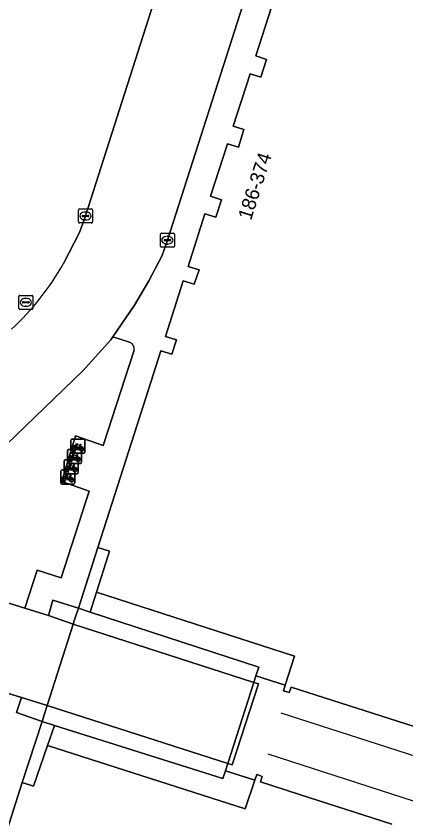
# Model space of a CAD drawing. Extents: x 160675 to 161153, y 383241 to 383714.
# Drawn here: x 160812.1 to 160839.9, y 383336.8 to 383394.1 of the extents above; entities that cross this region are included whole.
import ezdxf

# ---------------------------------------------------------------- set-up
doc = ezdxf.new("R2010")
doc.units = 0
for name, color, linetype in [('IMGEO_Brandkraan', 7, 'Continuous'), ('IMGEO_Erf', 7, 'Continuous'), ('IMGEO_Fietsenrek', 7, 'Continuous'), ('IMGEO_Grasland_overig', 7, 'Continuous'), ('IMGEO_Groenvoorziening', 7, 'Continuous'), ('IMGEO_Kolk', 7, 'Continuous'), ('IMGEO_Lijnafwatering', 7, 'Continuous'), ('IMGEO_Muur', 7, 'Continuous'), ('IMGEO_Pand', 7, 'Continuous'), ('IMGEO_Pand_nummerreeks', 7, 'Continuous'), ('IMGEO_Pand_overbouw', 7, 'Continuous'), ('IMGEO_Rijbaan_lokaal_gesloten', 7, 'Continuous'), ('IMGEO_Rijbaan_lokaal_open', 7, 'Continuous'), ('IMGEO_Voetpad_open', 7, 'Continuous')]:
    doc.layers.add(name, color=color, linetype=linetype)

msp = doc.modelspace()

# ---------------------------------------------------------------- linework, layer by layer
at = {"layer": 'IMGEO_Brandkraan'}
for p, q in [((160812.259, 383373.243), (160812.259, 383374.095)), ((160812.334, 383374.169), (160813.186, 383374.169)), ((160812.518, 383373.663), (160812.518, 383373.675)), ((160812.561, 383373.712), (160812.959, 383373.712)), ((160812.747, 383373.949), (160812.772, 383373.949)), ((160813.002, 383373.675), (160813.002, 383373.663)), ((160813.26, 383374.095), (160813.26, 383373.243)), ((160813.186, 383373.169), (160812.334, 383373.169)), ((160812.956, 383373.626), (160812.558, 383373.626)), ((160812.77, 383373.389), (160812.745, 383373.389))]:
    msp.add_line(p, q, dxfattribs=at)
for points in [[(160812.259, 383373.243), (160812.259, 383374.095)], [(160812.334, 383374.169), (160813.186, 383374.169)], [(160813.26, 383374.095), (160813.26, 383373.243)], [(160813.186, 383373.169), (160812.334, 383373.169)]]:
    msp.add_lwpolyline(points, dxfattribs=at)
for centre, radius, start, end in [((160812.336, 383374.093), 0.0765, 91.552, 178.448), ((160812.336, 383374.093), 0.0765, 91.552, 178.448), ((160812.558, 383373.672), 0.0403, 85.8775, 175.7526), ((160812.555, 383373.662), 0.0366, 178.938, 274.7102), ((160812.959, 383373.669), 0.043, 264.8664, 352.4533), ((160812.963, 383373.674), 0.0386, 1.7309, 96.639), ((160813.184, 383374.093), 0.0765, 1.552, 88.448), ((160813.184, 383374.093), 0.0765, 1.552, 88.448), ((160812.336, 383373.245), 0.0765, 181.552, 268.448), ((160812.336, 383373.245), 0.0765, 181.552, 268.448), ((160813.184, 383373.245), 0.0765, 271.552, 358.448), ((160813.184, 383373.245), 0.0765, 271.552, 358.448)]:
    msp.add_arc(centre, radius, start, end, dxfattribs=at)
for centre, major_axis, ratio, start_param, end_param in [((160812.746, 383373.669), (-0.387, 0.002), 0.722429, 4.712389, 7.853982), ((160812.771, 383373.669), (-0.39, 0.002), 0.717154, 1.570796, 4.712389)]:
    msp.add_ellipse(centre, major_axis=major_axis, ratio=ratio, start_param=start_param, end_param=end_param, dxfattribs=at)
at = {"layer": 'IMGEO_Erf'}
msp.add_lwpolyline([(160815.453, 383376.434), (160816.581, 383378.652), (160817.019, 383379.826), (160822.806, 383397.984)], dxfattribs=at)
msp.add_arc((160797.755, 383386.651), 20.436, 313.2153, 330.002, dxfattribs=at)
at = {"layer": 'IMGEO_Fietsenrek'}
for p, q in [((160816.041, 383363.919), (160816.882, 383363.919)), ((160816.882, 383363.919), (160816.041, 383363.919)), ((160815.966, 383362.994), (160815.966, 383363.835)), ((160815.966, 383363.835), (160815.966, 383362.994)), ((160816.653, 383363.468), (160816.689, 383363.373)), ((160816.966, 383363.844), (160816.966, 383363.003)), ((160816.966, 383363.003), (160816.966, 383363.844)), ((160815.728, 383362.262), (160815.728, 383363.103)), ((160815.728, 383363.103), (160815.728, 383362.262)), ((160815.803, 383363.187), (160816.644, 383363.187)), ((160816.644, 383363.187), (160815.803, 383363.187)), ((160816.891, 383362.919), (160816.05, 383362.919)), ((160816.05, 383362.919), (160816.891, 383362.919)), ((160816.093, 383363.003), (160816.132, 383363.163)), ((160816.127, 383363.003), (160816.093, 383363.003)), ((160816.162, 383363.151), (160816.127, 383363.003)), ((160816.204, 383363.175), (160816.203, 383363.179)), ((160816.245, 383363.003), (160816.211, 383363.145)), ((160816.235, 383363.186), (160816.236, 383363.179)), ((160816.243, 383363.149), (160816.278, 383363.003)), ((160816.278, 383363.003), (160816.245, 383363.003)), ((160816.728, 383363.112), (160816.728, 383362.271)), ((160816.728, 383362.271), (160816.728, 383363.112)), ((160815.491, 383361.53), (160815.491, 383362.371)), ((160815.491, 383362.371), (160815.491, 383361.53)), ((160815.566, 383362.455), (160816.407, 383362.455)), ((160816.407, 383362.455), (160815.566, 383362.455)), ((160815.855, 383362.271), (160815.894, 383362.431)), ((160815.889, 383362.271), (160815.855, 383362.271)), ((160815.924, 383362.419), (160815.889, 383362.271)), ((160815.966, 383362.443), (160815.965, 383362.447)), ((160816.007, 383362.271), (160815.973, 383362.413)), ((160815.997, 383362.454), (160815.998, 383362.447)), ((160816.005, 383362.417), (160816.04, 383362.271)), ((160816.04, 383362.271), (160816.007, 383362.271)), ((160816.415, 383362.736), (160816.451, 383362.641)), ((160816.491, 383362.38), (160816.491, 383361.539)), ((160816.491, 383361.539), (160816.491, 383362.38)), ((160815.253, 383360.798), (160815.253, 383361.639)), ((160815.253, 383361.639), (160815.253, 383360.798)), ((160815.328, 383361.723), (160816.169, 383361.723)), ((160816.169, 383361.723), (160815.328, 383361.723)), ((160815.618, 383361.539), (160815.657, 383361.699)), ((160815.687, 383361.687), (160815.652, 383361.539)), ((160815.729, 383361.711), (160815.728, 383361.715)), ((160815.77, 383361.539), (160815.736, 383361.681)), ((160815.76, 383361.722), (160815.761, 383361.715)), ((160815.768, 383361.685), (160815.803, 383361.539)), ((160816.653, 383362.187), (160815.812, 383362.187)), ((160815.812, 383362.187), (160816.653, 383362.187)), ((160816.178, 383362.004), (160816.214, 383361.909)), ((160816.253, 383361.648), (160816.253, 383360.807)), ((160816.253, 383360.807), (160816.253, 383361.648)), ((160816.416, 383361.455), (160815.575, 383361.455)), ((160815.575, 383361.455), (160816.416, 383361.455)), ((160815.652, 383361.539), (160815.618, 383361.539)), ((160815.803, 383361.539), (160815.77, 383361.539)), ((160815.94, 383361.272), (160815.976, 383361.177)), ((160816.178, 383360.723), (160815.337, 383360.723)), ((160815.337, 383360.723), (160816.178, 383360.723)), ((160815.38, 383360.807), (160815.419, 383360.967)), ((160815.414, 383360.807), (160815.38, 383360.807)), ((160815.449, 383360.955), (160815.414, 383360.807)), ((160815.491, 383360.979), (160815.49, 383360.983)), ((160815.532, 383360.807), (160815.498, 383360.949)), ((160815.522, 383360.99), (160815.523, 383360.983)), ((160815.53, 383360.953), (160815.565, 383360.807)), ((160815.565, 383360.807), (160815.532, 383360.807))]:
    msp.add_line(p, q, dxfattribs=at)
for points in [[(160816.3, 383363.393), (160816.248, 383363.303), (160816.208, 383363.278), (160816.209, 383363.325), (160816.264, 383363.419)], [(160816.279, 383363.445), (160816.374, 383363.609), (160816.46, 383363.595), (160816.462, 383363.586), (160816.406, 383363.575), (160816.379, 383363.53), (160816.635, 383363.489)], [(160816.575, 383363.201), (160816.525, 383363.201), (160816.334, 383363.452), (160816.315, 383363.42)], [(160816.622, 383363.464), (160816.365, 383363.505), (160816.348, 383363.476), (160816.515, 383363.256), (160816.622, 383363.464)], [(160816.67, 383363.366), (160816.64, 383363.443), (160816.531, 383363.225), (160816.574, 383363.225)], [(160816.604, 383363.225), (160816.724, 383363.224), (160816.68, 383363.338)], [(160816.7, 383363.345), (160816.755, 383363.2), (160816.605, 383363.2)], [(160816.635, 383363.489), (160816.66, 383363.538), (160816.654, 383363.542), (160816.631, 383363.546), (160816.619, 383363.553), (160816.618, 383363.556), (160816.62, 383363.561), (160816.715, 383363.546), (160816.717, 383363.536), (160816.707, 383363.523), (160816.695, 383363.517), (160816.681, 383363.523), (160816.653, 383363.468)], [(160816.041, 383362.713), (160816.136, 383362.877), (160816.222, 383362.863), (160816.224, 383362.854), (160816.168, 383362.843), (160816.141, 383362.798), (160816.397, 383362.757)], [(160816.384, 383362.732), (160816.127, 383362.773), (160816.11, 383362.744), (160816.277, 383362.524), (160816.384, 383362.732)], [(160816.397, 383362.757), (160816.422, 383362.806), (160816.416, 383362.81), (160816.393, 383362.814), (160816.381, 383362.821), (160816.38, 383362.824), (160816.382, 383362.829), (160816.477, 383362.814), (160816.479, 383362.804), (160816.469, 383362.791), (160816.457, 383362.785), (160816.443, 383362.791), (160816.415, 383362.736)], [(160816.062, 383362.661), (160816.01, 383362.571), (160815.97, 383362.546), (160815.971, 383362.593), (160816.026, 383362.687)], [(160816.337, 383362.469), (160816.287, 383362.469), (160816.096, 383362.72), (160816.077, 383362.688)], [(160816.432, 383362.634), (160816.402, 383362.711), (160816.293, 383362.493), (160816.336, 383362.493)], [(160816.366, 383362.493), (160816.486, 383362.492), (160816.442, 383362.606)], [(160816.462, 383362.613), (160816.517, 383362.468), (160816.367, 383362.468)], [(160815.825, 383361.929), (160815.773, 383361.839), (160815.733, 383361.814), (160815.734, 383361.861), (160815.789, 383361.955)], [(160815.804, 383361.981), (160815.899, 383362.145), (160815.985, 383362.131), (160815.987, 383362.122), (160815.931, 383362.111), (160815.904, 383362.066), (160816.16, 383362.025)], [(160816.1, 383361.737), (160816.05, 383361.737), (160815.859, 383361.988), (160815.84, 383361.956)], [(160816.147, 383362), (160815.89, 383362.041), (160815.873, 383362.012), (160816.04, 383361.792), (160816.147, 383362)], [(160816.195, 383361.902), (160816.165, 383361.979), (160816.056, 383361.761), (160816.099, 383361.761)], [(160816.129, 383361.761), (160816.249, 383361.76), (160816.205, 383361.874)], [(160816.225, 383361.881), (160816.28, 383361.736), (160816.13, 383361.736)], [(160816.16, 383362.025), (160816.185, 383362.074), (160816.179, 383362.078), (160816.156, 383362.082), (160816.144, 383362.089), (160816.143, 383362.092), (160816.145, 383362.097), (160816.24, 383362.082), (160816.242, 383362.072), (160816.232, 383362.059), (160816.22, 383362.053), (160816.206, 383362.059), (160816.178, 383362.004)], [(160815.587, 383361.197), (160815.535, 383361.107), (160815.495, 383361.082), (160815.496, 383361.129), (160815.551, 383361.223)], [(160815.566, 383361.249), (160815.661, 383361.413), (160815.747, 383361.399), (160815.749, 383361.39), (160815.693, 383361.379), (160815.666, 383361.334), (160815.922, 383361.293)], [(160815.862, 383361.005), (160815.812, 383361.005), (160815.621, 383361.256), (160815.602, 383361.224)], [(160815.909, 383361.268), (160815.652, 383361.309), (160815.635, 383361.28), (160815.802, 383361.06), (160815.909, 383361.268)], [(160815.957, 383361.17), (160815.927, 383361.247), (160815.818, 383361.029), (160815.861, 383361.029)], [(160815.891, 383361.029), (160816.011, 383361.028), (160815.967, 383361.142)], [(160815.987, 383361.149), (160816.042, 383361.004), (160815.892, 383361.004)], [(160815.922, 383361.293), (160815.947, 383361.342), (160815.941, 383361.346), (160815.918, 383361.35), (160815.906, 383361.357), (160815.905, 383361.36), (160815.907, 383361.365), (160816.002, 383361.35), (160816.004, 383361.34), (160815.994, 383361.327), (160815.982, 383361.321), (160815.968, 383361.327), (160815.94, 383361.272)]]:
    msp.add_lwpolyline(points, dxfattribs=at)
for centre, radius, start, end in [((160816.044, 383363.841), 0.0779, 92.4484, 184.2845), ((160816.044, 383363.841), 0.0779, 92.4484, 184.2845), ((160816.888, 383363.841), 0.0779, 2.4484, 94.2845), ((160816.888, 383363.841), 0.0779, 2.4484, 94.2845), ((160816.206, 383363.304), 0.159, 62.6766, 242.1369), ((160816.206, 383363.304), 0.129, 63.3192, 238.903), ((160816.206, 383363.304), 0.129, 283.6043, 43.4302), ((160816.206, 383363.304), 0.159, 283.5766, 46.6042), ((160816.733, 383363.22), 0.159, 113.3408, 178.3217), ((160816.733, 383363.22), 0.159, 187.0065, 105.7708), ((160816.733, 383363.22), 0.129, 113.923, 177.9556), ((160816.733, 383363.22), 0.129, 188.6715, 104.5883), ((160815.806, 383363.109), 0.0779, 92.4484, 184.2845), ((160815.806, 383363.109), 0.0779, 92.4484, 184.2845), ((160816.044, 383362.997), 0.0779, 182.4484, 274.2845), ((160816.044, 383362.997), 0.0779, 182.4484, 274.2845), ((160816.186, 383363.175), 0.0499, 12.8025, 158.6934), ((160816.206, 383363.304), 0.159, 253.9967, 271.7867), ((160816.186, 383363.175), 0.0174, 12.8025, 163.4502), ((160816.206, 383363.304), 0.129, 253.415, 269.0204), ((160816.65, 383363.109), 0.0779, 2.4484, 94.2845), ((160816.65, 383363.109), 0.0779, 2.4484, 94.2845), ((160816.888, 383362.997), 0.0779, 272.4484, 4.2845), ((160816.888, 383362.997), 0.0779, 272.4484, 4.2845), ((160815.569, 383362.377), 0.0779, 92.4484, 184.2845), ((160815.569, 383362.377), 0.0779, 92.4484, 184.2845), ((160815.806, 383362.265), 0.0779, 182.4484, 274.2845), ((160815.806, 383362.265), 0.0779, 182.4484, 274.2845), ((160815.968, 383362.572), 0.159, 62.6766, 242.1369), ((160815.968, 383362.572), 0.129, 63.3192, 238.903), ((160815.948, 383362.443), 0.0499, 12.8025, 158.6934), ((160815.968, 383362.572), 0.159, 253.9967, 271.7867), ((160815.948, 383362.443), 0.0174, 12.8025, 163.4502), ((160815.968, 383362.572), 0.129, 253.415, 269.0204), ((160815.968, 383362.572), 0.129, 283.6043, 43.4302), ((160815.968, 383362.572), 0.159, 283.5766, 46.6042), ((160816.495, 383362.488), 0.159, 113.3408, 178.3217), ((160816.495, 383362.488), 0.159, 187.0065, 105.7708), ((160816.495, 383362.488), 0.129, 113.923, 177.9556), ((160816.495, 383362.488), 0.129, 188.6715, 104.5883), ((160816.413, 383362.377), 0.0779, 2.4484, 94.2845), ((160816.413, 383362.377), 0.0779, 2.4484, 94.2845), ((160816.65, 383362.265), 0.0779, 272.4484, 4.2845), ((160816.65, 383362.265), 0.0779, 272.4484, 4.2845), ((160815.331, 383361.645), 0.0779, 92.4484, 184.2845), ((160815.331, 383361.645), 0.0779, 92.4484, 184.2845), ((160815.731, 383361.84), 0.159, 62.6766, 242.1369), ((160815.731, 383361.84), 0.129, 63.3192, 238.903), ((160815.711, 383361.711), 0.0499, 12.8025, 158.6934), ((160815.731, 383361.84), 0.159, 253.9967, 271.7867), ((160815.711, 383361.711), 0.0174, 12.8025, 163.4502), ((160815.731, 383361.84), 0.129, 253.415, 269.0204), ((160815.731, 383361.84), 0.129, 283.6043, 43.4302), ((160815.731, 383361.84), 0.159, 283.5766, 46.6042), ((160816.258, 383361.756), 0.159, 113.3408, 178.3217), ((160816.258, 383361.756), 0.159, 187.0065, 105.7708), ((160816.258, 383361.756), 0.129, 113.923, 177.9556), ((160816.258, 383361.756), 0.129, 188.6715, 104.5883), ((160816.175, 383361.645), 0.0779, 2.4484, 94.2845), ((160816.175, 383361.645), 0.0779, 2.4484, 94.2845), ((160815.493, 383361.108), 0.159, 62.6766, 242.1369), ((160815.493, 383361.108), 0.129, 63.3192, 238.903), ((160815.569, 383361.533), 0.0779, 182.4484, 274.2845), ((160815.569, 383361.533), 0.0779, 182.4484, 274.2845), ((160815.493, 383361.108), 0.129, 283.6043, 43.4302), ((160815.493, 383361.108), 0.159, 283.5766, 46.6042), ((160816.02, 383361.024), 0.159, 113.3408, 178.3217), ((160816.02, 383361.024), 0.159, 187.0065, 105.7708), ((160816.02, 383361.024), 0.129, 113.923, 177.9556), ((160816.02, 383361.024), 0.129, 188.6715, 104.5883), ((160816.413, 383361.533), 0.0779, 272.4484, 4.2845), ((160816.413, 383361.533), 0.0779, 272.4484, 4.2845), ((160815.331, 383360.801), 0.0779, 182.4484, 274.2845), ((160815.331, 383360.801), 0.0779, 182.4484, 274.2845), ((160815.473, 383360.979), 0.0499, 12.8025, 158.6934), ((160815.493, 383361.108), 0.159, 253.9967, 271.7867), ((160815.473, 383360.979), 0.0174, 12.8025, 163.4502), ((160815.493, 383361.108), 0.129, 253.415, 269.0204), ((160816.175, 383360.801), 0.0779, 272.4484, 4.2845), ((160816.175, 383360.801), 0.0779, 272.4484, 4.2845)]:
    msp.add_arc(centre, radius, start, end, dxfattribs=at)
at = {"layer": 'IMGEO_Grasland_overig'}
for points in [[(160816.262, 383351.119), (160816.527, 383351.866), (160814.697, 383352.441), (160814.381, 383351.347), (160816.128, 383350.738)], [(160814.279, 383344.95), (160812.457, 383345.502), (160812.099, 383344.43), (160813.938, 383343.795), (160814.1, 383344.346)]]:
    msp.add_lwpolyline(points, close=True, dxfattribs=at)
at = {"layer": 'IMGEO_Groenvoorziening'}
for points in [[(160820.15, 383370.824), (160818.954, 383371.207), (160818.816, 383371.007), (160816.836, 383368.789), (160806.548, 383358.908), (160806.021, 383358.402)], [(160806.701, 383353.778), (160810.777, 383352.46), (160812.694, 383351.868), (160813.56, 383354.584), (160815.278, 383354.045), (160817.277, 383360.223), (160815.328, 383360.895), (160816.31, 383364.162), (160818.286, 383363.462), (160820.49, 383370.251)]]:
    msp.add_lwpolyline(points, dxfattribs=at)
msp.add_arc((160820.021, 383370.36), 0.481, 346.9032, 74.4639, dxfattribs=at)
at = {"layer": 'IMGEO_Kolk'}
for p, q in [((160816.518, 383379.4), (160816.518, 383380.252)), ((160816.593, 383380.326), (160817.445, 383380.326)), ((160817.006, 383380.106), (160817.031, 383380.106)), ((160817.519, 383380.252), (160817.519, 383379.4)), ((160816.777, 383379.82), (160816.777, 383379.832)), ((160817.215, 383379.783), (160816.817, 383379.783)), ((160816.82, 383379.869), (160817.218, 383379.869)), ((160817.029, 383379.546), (160817.004, 383379.546)), ((160817.261, 383379.832), (160817.261, 383379.82)), ((160817.445, 383379.326), (160816.593, 383379.326)), ((160822.356, 383377.677), (160822.356, 383378.529)), ((160822.431, 383378.603), (160823.283, 383378.603)), ((160822.844, 383378.383), (160822.869, 383378.383)), ((160823.357, 383378.529), (160823.357, 383377.677)), ((160822.615, 383378.097), (160822.615, 383378.109)), ((160823.053, 383378.06), (160822.655, 383378.06)), ((160822.658, 383378.146), (160823.056, 383378.146)), ((160822.867, 383377.823), (160822.842, 383377.823)), ((160823.099, 383378.109), (160823.099, 383378.097)), ((160823.283, 383377.603), (160822.431, 383377.603))]:
    msp.add_line(p, q, dxfattribs=at)
for points in [[(160816.518, 383379.4), (160816.518, 383380.252)], [(160816.593, 383380.326), (160817.445, 383380.326)], [(160817.519, 383380.252), (160817.519, 383379.4)], [(160817.445, 383379.326), (160816.593, 383379.326)], [(160822.356, 383377.677), (160822.356, 383378.529)], [(160822.431, 383378.603), (160823.283, 383378.603)], [(160823.357, 383378.529), (160823.357, 383377.677)], [(160823.283, 383377.603), (160822.431, 383377.603)]]:
    msp.add_lwpolyline(points, dxfattribs=at)
for centre, radius, start, end in [((160816.595, 383380.25), 0.0765, 91.552, 178.448), ((160816.595, 383380.25), 0.0765, 91.552, 178.448), ((160817.443, 383380.25), 0.0765, 1.552, 88.448), ((160817.443, 383380.25), 0.0765, 1.552, 88.448), ((160816.595, 383379.402), 0.0765, 181.552, 268.448), ((160816.595, 383379.402), 0.0765, 181.552, 268.448), ((160816.817, 383379.829), 0.0403, 85.8775, 175.7526), ((160816.814, 383379.819), 0.0366, 178.938, 274.7102), ((160817.218, 383379.826), 0.043, 264.8664, 352.4533), ((160817.222, 383379.831), 0.0386, 1.7309, 96.639), ((160817.443, 383379.402), 0.0765, 271.552, 358.448), ((160817.443, 383379.402), 0.0765, 271.552, 358.448), ((160822.433, 383378.527), 0.0765, 91.552, 178.448), ((160822.433, 383378.527), 0.0765, 91.552, 178.448), ((160823.281, 383378.527), 0.0765, 1.552, 88.448), ((160823.281, 383378.527), 0.0765, 1.552, 88.448), ((160822.433, 383377.679), 0.0765, 181.552, 268.448), ((160822.433, 383377.679), 0.0765, 181.552, 268.448), ((160822.655, 383378.106), 0.0403, 85.8775, 175.7526), ((160822.652, 383378.096), 0.0366, 178.938, 274.7102), ((160823.056, 383378.103), 0.043, 264.8664, 352.4533), ((160823.06, 383378.108), 0.0386, 1.7309, 96.639), ((160823.281, 383377.679), 0.0765, 271.552, 358.448), ((160823.281, 383377.679), 0.0765, 271.552, 358.448)]:
    msp.add_arc(centre, radius, start, end, dxfattribs=at)
for centre, major_axis, ratio, start_param, end_param in [((160817.005, 383379.826), (-0.387, 0.002), 0.722429, 4.712389, 7.853982), ((160817.03, 383379.826), (-0.39, 0.002), 0.717154, 1.570796, 4.712389), ((160822.843, 383378.103), (-0.387, 0.002), 0.722429, 4.712389, 7.853982), ((160822.868, 383378.103), (-0.39, 0.002), 0.717154, 1.570796, 4.712389)]:
    msp.add_ellipse(centre, major_axis=major_axis, ratio=ratio, start_param=start_param, end_param=end_param, dxfattribs=at)
at = {"layer": 'IMGEO_Lijnafwatering'}
for points in [[(160849.732, 383338.36), (160830.959, 383344.395)], [(160847.617, 383335.798), (160830.048, 383341.461)]]:
    msp.add_lwpolyline(points, dxfattribs=at)
at = {"layer": 'IMGEO_Muur'}
msp.add_lwpolyline([(160827.157, 383340.806), (160827.467, 383340.706), (160829.359, 383346.481), (160829.019, 383346.59)], close=True, dxfattribs=at)
at = {"layer": 'IMGEO_Pand'}
for points in [[(160830.284, 383394.706), (160829.159, 383391.238), (160829.929, 383390.988), (160829.527, 383389.713), (160828.756, 383389.963), (160827.546, 383386.235), (160828.316, 383385.985), (160827.92, 383384.724), (160827.15, 383384.974), (160825.937, 383381.229), (160826.707, 383380.979), (160826.306, 383379.742), (160825.534, 383379.988), (160824.338, 383376.235), (160825.11, 383375.989), (160824.758, 383374.958), (160823.986, 383375.204), (160822.724, 383371.243), (160823.496, 383370.997), (160823.163, 383369.973), (160822.392, 383370.22), (160821.316, 383366.858), (160817.895, 383356.208), (160818.738, 383355.941), (160818.474, 383355.112), (160817.804, 383353.008), (160831.926, 383348.464), (160831.263, 383346.385), (160831.136, 383345.987), (160831.542, 383345.857), (160831.67, 383346.257), (160841.04, 383343.261)], [(160838.871, 383336.492), (160832.267, 383338.602), (160829.489, 383339.49), (160829.624, 383339.888), (160829.384, 383339.967), (160829.233, 383340.016), (160829.097, 383339.614), (160828.408, 383337.572), (160814.299, 383342.092), (160813.316, 383339.185), (160812.507, 383339.449), (160809.099, 383328.814)]]:
    msp.add_lwpolyline(points, dxfattribs=at)
for points in [[(160817.34, 383351.6), (160816.527, 383351.866), (160816.262, 383351.119), (160816.128, 383350.738), (160829.019, 383346.59), (160829.166, 383347.047), (160829.365, 383347.666)], [(160814.279, 383344.95), (160814.1, 383344.346), (160813.938, 383343.795), (160814.799, 383343.524), (160826.818, 383339.731), (160826.991, 383340.278), (160827.157, 383340.806)]]:
    msp.add_lwpolyline(points, close=True, dxfattribs=at)
at = {"layer": 'IMGEO_Pand_overbouw'}
for points in [[(160816.527, 383351.866), (160817.34, 383351.6), (160829.365, 383347.666), (160829.166, 383347.047), (160831.263, 383346.385), (160831.926, 383348.464), (160817.804, 383353.008), (160818.474, 383355.112), (160818.738, 383355.941), (160817.895, 383356.208)], [(160826.991, 383340.278), (160826.818, 383339.731), (160814.799, 383343.524), (160813.938, 383343.795), (160812.507, 383339.449), (160813.316, 383339.185), (160814.299, 383342.092), (160828.408, 383337.572), (160829.097, 383339.614)]]:
    msp.add_lwpolyline(points, close=True, dxfattribs=at)
at = {"layer": 'IMGEO_Rijbaan_lokaal_gesloten'}
msp.add_lwpolyline([(160829.019, 383346.59), (160816.128, 383350.738), (160814.279, 383344.95), (160827.157, 383340.806)], close=True, dxfattribs=at)
at = {"layer": 'IMGEO_Rijbaan_lokaal_open'}
for points in [[(160835.925, 383424.95), (160839.351, 383433.584), (160834.558, 383435.125), (160833.651, 383432.112), (160831.814, 383426.328), (160828.462, 383415.776), (160822.806, 383397.984), (160817.019, 383379.826), (160816.581, 383378.652), (160815.453, 383376.434)], [(160816.836, 383368.789), (160818.816, 383371.007), (160818.954, 383371.207), (160820.52, 383373.47), (160821.528, 383375.201), (160822.464, 383376.968), (160822.857, 383378.103), (160828.642, 383396.124), (160834.694, 383414.833), (160835.38, 383416.978)], [(160806.021, 383358.402), (160806.548, 383358.908), (160816.836, 383368.789)], [(160804.384, 383348.108), (160808.782, 383346.694), (160810.812, 383346.001), (160812.457, 383345.502), (160814.279, 383344.95), (160816.128, 383350.738), (160814.381, 383351.347), (160812.694, 383351.868), (160810.777, 383352.46), (160806.701, 383353.778)]]:
    msp.add_lwpolyline(points, dxfattribs=at)
msp.add_arc((160797.755, 383386.651), 20.436, 313.2153, 330.002, dxfattribs=at)
at = {"layer": 'IMGEO_Voetpad_open'}
for points in [[(160898.106, 383394.467), (160869.425, 383403.701), (160870.118, 383405.788), (160870.773, 383407.909), (160867.624, 383408.896), (160866.952, 383406.817), (160866.327, 383404.687), (160850.434, 383409.78), (160851.186, 383411.909), (160851.814, 383414.001), (160848.706, 383415.007), (160847.995, 383412.915), (160845.177, 383413.825), (160844.501, 383411.704), (160834.694, 383414.833), (160828.642, 383396.124), (160822.857, 383378.103), (160822.464, 383376.968), (160821.528, 383375.201), (160820.52, 383373.47), (160818.954, 383371.207), (160820.15, 383370.824)], [(160820.49, 383370.251), (160818.286, 383363.462), (160816.31, 383364.162), (160815.328, 383360.895), (160817.277, 383360.223), (160815.278, 383354.045), (160813.56, 383354.584), (160812.694, 383351.868), (160814.381, 383351.347), (160814.697, 383352.441), (160816.527, 383351.866), (160817.895, 383356.208), (160821.316, 383366.858), (160822.392, 383370.22), (160823.163, 383369.973), (160823.496, 383370.997), (160822.724, 383371.243), (160823.986, 383375.204), (160824.758, 383374.958), (160825.11, 383375.989), (160824.338, 383376.235), (160825.534, 383379.988), (160826.306, 383379.742), (160826.707, 383380.979), (160825.937, 383381.229), (160827.15, 383384.974), (160827.92, 383384.724), (160828.316, 383385.985), (160827.546, 383386.235), (160828.756, 383389.963), (160829.527, 383389.713), (160829.929, 383390.988), (160829.159, 383391.238), (160830.284, 383394.706)], [(160867.043, 383334.896), (160842.086, 383342.926), (160841.04, 383343.261), (160831.67, 383346.257), (160831.542, 383345.857), (160831.136, 383345.987), (160831.263, 383346.385), (160829.166, 383347.047), (160829.019, 383346.59), (160829.359, 383346.481), (160827.467, 383340.706), (160827.157, 383340.806), (160826.991, 383340.278), (160829.097, 383339.614), (160829.233, 383340.016), (160829.384, 383339.967), (160829.624, 383339.888), (160829.489, 383339.49), (160832.267, 383338.602), (160838.871, 383336.492)], [(160809.099, 383328.814), (160812.507, 383339.449), (160813.938, 383343.795), (160812.099, 383344.43), (160812.457, 383345.502), (160810.812, 383346.001)]]:
    msp.add_lwpolyline(points, dxfattribs=at)
for points in [[(160817.34, 383351.6), (160817.804, 383353.008), (160818.474, 383355.112), (160818.738, 383355.941), (160817.895, 383356.208), (160816.527, 383351.866)], [(160817.804, 383353.008), (160817.34, 383351.6), (160829.365, 383347.666), (160829.166, 383347.047), (160831.263, 383346.385), (160831.926, 383348.464)], [(160813.938, 383343.795), (160812.507, 383339.449), (160813.316, 383339.185), (160814.299, 383342.092), (160814.799, 383343.524)], [(160829.097, 383339.614), (160826.991, 383340.278), (160826.818, 383339.731), (160814.799, 383343.524), (160814.299, 383342.092), (160828.408, 383337.572)]]:
    msp.add_lwpolyline(points, close=True, dxfattribs=at)
msp.add_arc((160820.021, 383370.36), 0.481, 346.9032, 74.4639, dxfattribs=at)

# ---------------------------------------------------------------- texts
at = {"layer": 'IMGEO_Pand_nummerreeks'}
msp.add_text('186-374', height=1, rotation=72.2117, dxfattribs=at).set_placement((160828.814, 383379.468))

doc.saveas('drawing.dxf')
